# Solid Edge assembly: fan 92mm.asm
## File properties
Author: Julian Frimmel
Template: Iso Metric Assembly.asm
Last saved by: Julian Frimmel
Revision: 4
Application: Solid Edge
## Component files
fan form.par
fan.par
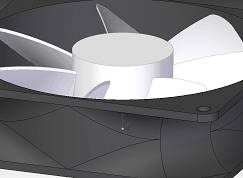
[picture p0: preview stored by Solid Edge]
